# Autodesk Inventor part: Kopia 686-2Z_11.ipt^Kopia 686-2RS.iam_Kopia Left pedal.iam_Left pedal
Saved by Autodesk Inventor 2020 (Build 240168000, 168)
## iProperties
Created: 2017-10
Part Number: Kopia 686-2Z_11.ipt^Kopia 686-2RS.iam_Kopia Left pedal.iam_Left pedal
Material: Ogólny
Document SubType Name: Modeling
Designer: Tomasz
Density: 1 g/cm^3
Appearance: Domyślna
Sending System: SolidWorks 2017
Last Author: Tomasz
Last Saved: 2017-10-01
Author: Tomasz
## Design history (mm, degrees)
